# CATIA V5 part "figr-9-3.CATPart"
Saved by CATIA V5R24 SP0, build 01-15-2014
Part number: Part1
Bounding box of the stored display mesh (mm): x -25 to 69.61, y -164.735 to 0, z 0 to 45
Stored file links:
  D:\KAVITA\CATIA V5-6R2014 Project_ Kavita\CATIA V5-6R2014_partfiles\Partfiles\c09_catia_v5-6r2014_prt\figr-9-3.CATPart
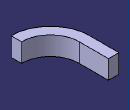
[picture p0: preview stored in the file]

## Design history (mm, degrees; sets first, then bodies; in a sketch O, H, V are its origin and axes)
Body1 (main body)
  Sketch1 on xy-plane, origin (0, 0, 0), H (1, 0, 0), V (0, 1, 0)
    line L1 (0, 0) -> (0, -70.1255)
    arc A1 centre (69.6095, -70.1255) radius 69.6095 from (0, -70.1255) to (69.6095, -139.7351) ccw
    vertical: L1 V
    tangency: A1 L1
  Sketch2 on zx-plane, origin (0, 0, 0), H (-1, 0, 0), V (0, 0, 1)
    point P1 (0, 0)
    line L1 (0, 0) -> (25, 0)
    line L2 (25, 0) -> (25, 45)
    line L3 (25, 45) -> (0, 45)
    line L4 (0, 45) -> (0, 0)
    length L3 = 25
    length L2 = 45
    coincidence: P1 H, P1 O
    horizontal: L1 H, L3 H
    vertical: L2 V, L4 V
  Rib1: profile Sketch2, centre curve Sketch1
